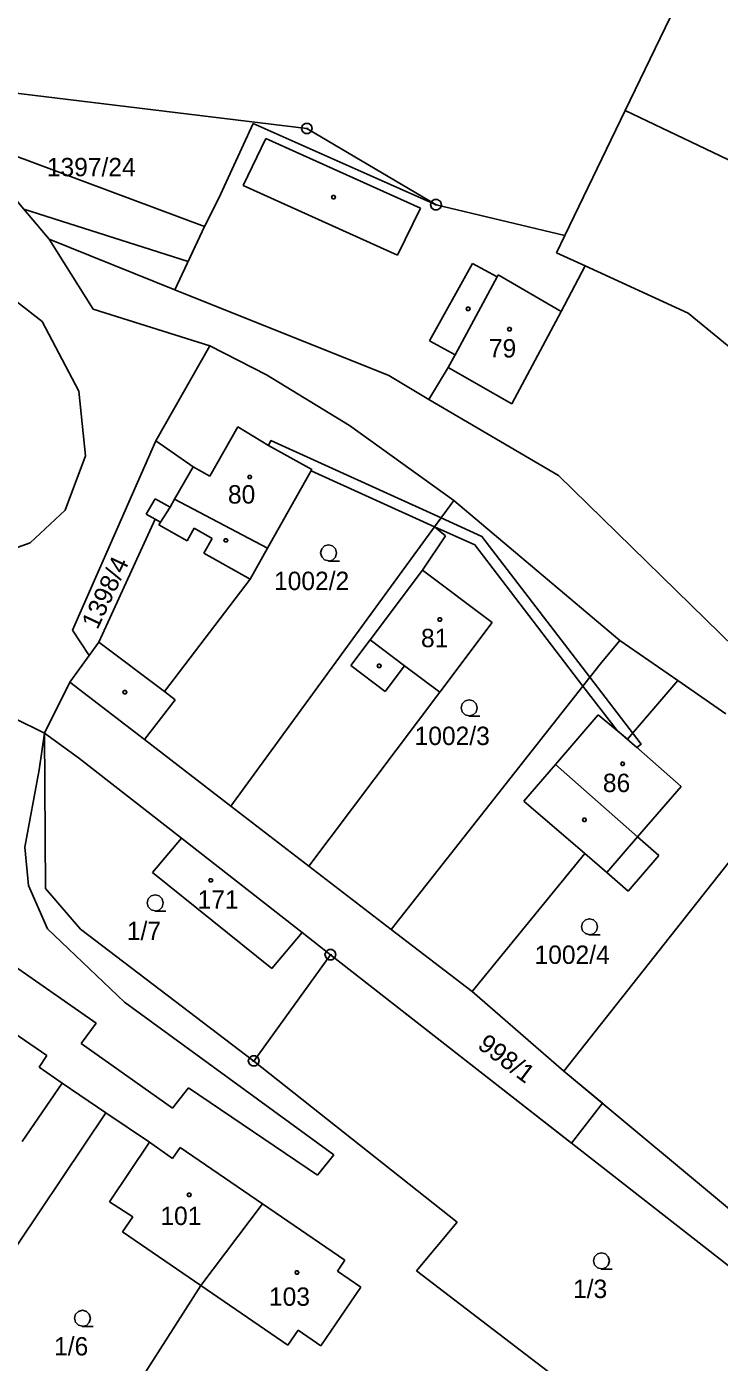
# Model space of a CAD drawing. Extents: x -850689 to -847910, y -1058374 to -1054747.
# Drawn here: x -849251.2 to -849187.1, y -1056373.6 to -1056250.1 of the extents above; entities that cross this region are included whole.
import ezdxf

# ---------------------------------------------------------------- set-up
doc = ezdxf.new("R2010")
doc.units = 0
for name, color, linetype in [('KN_BREMENA', 7, 'Continuous'), ('KN_HRANICE', 7, 'Continuous'), ('KN_KULTURY', 7, 'Continuous'), ('KN_MEZNIKY', 7, 'Continuous'), ('KN_PARCELY', 7, 'Continuous'), ('KN_SLUCKY', 7, 'Continuous'), ('KN_STAVEBNI', 7, 'Continuous')]:
    doc.layers.add(name, color=color, linetype=linetype)

# ---------------------------------------------------------------- blocks, each defined once
blk = doc.blocks.new('304')
blk.add_lwpolyline([(0, 0), (-0.38, 0.1), (-0.65, 0.37), (-0.75, 0.74), (-0.65, 1.11), (-0.38, 1.38), (-0.01, 1.48), (0.36, 1.38), (0.63, 1.11), (0.73, 0.73), (0.63, 0.35), (0.36, 0.08), (-0.02, -0.02), (0.98, -0.02)])
blk = doc.blocks.new('402')
blk.add_lwpolyline([(0.09, 0.15), (0.18, 0), (0.09, -0.15), (-0.09, -0.15), (-0.18, 0), (-0.09, 0.15), (0.09, 0.15)])
blk = doc.blocks.new('105')
blk.add_line((-0.12, 0), (0.12, 0))
blk.add_lwpolyline([(0.15, 0.48), (0.4, 0.3), (0.5, 0.01), (0.4, -0.28), (0.15, -0.46), (-0.16, -0.46), (-0.41, -0.28), (-0.51, 0.01), (-0.41, 0.3), (-0.16, 0.48), (0.15, 0.48)])

msp = doc.modelspace()

# ---------------------------------------------------------------- linework, layer by layer
at = {"layer": 'KN_BREMENA'}
for points in [[(-849236.23, -1056271.84), (-849251.43, -1056266.98), (-849257.13, -1056260.24), (-849234.71, -1056268.6)], [(-849228.79, -1056288.86), (-849228.58, -1056288.4), (-849212.84, -1056295.54), (-849213.44, -1056296.36), (-849224.86, -1056291.18), (-849224.8, -1056291.07)], [(-849199.73, -1056311.09), (-849209.71, -1056298.05), (-849213.44, -1056296.36), (-849212.84, -1056295.54), (-849209.07, -1056297.25), (-849199.09, -1056310.27)], [(-849247.18, -1056310.75), (-849240.27, -1056316.03), (-849232.27, -1056322.21), (-849225.06, -1056327.75), (-849217.45, -1056333.6), (-849209.96, -1056339.35), (-849201.5, -1056346.7), (-849197.93, -1056349.68), (-849200.78, -1056353.37), (-849223.07, -1056335.94), (-849225.69, -1056333.89), (-849236.86, -1056325.16), (-849246.38, -1056317.74), (-849249.52, -1056315.45)], [(-849199.09, -1056310.27), (-849194.34, -1056316.47), (-849194.73, -1056316.77), (-849196.56, -1056315.22), (-849199.73, -1056311.09)]]:
    msp.add_lwpolyline(points, close=True, dxfattribs=at)
at = {"layer": 'KN_HRANICE'}
for p, q in [((-849187.73, -1056241.12), (-849195.81, -1056257.87)), ((-849261.46, -1056255.12), (-849225.25, -1056259.54)), ((-849195.81, -1056257.87), (-849201.39, -1056269.43)), ((-849195.81, -1056257.87), (-849167.34, -1056271.45)), ((-849230.23, -1056259.07), (-849233.42, -1056266.05)), ((-849230.23, -1056259.07), (-849213.31, -1056266.59)), ((-849225.25, -1056259.54), (-849213.31, -1056266.59)), ((-849233.42, -1056266.05), (-849234.71, -1056268.6)), ((-849251.43, -1056266.98), (-849249.09, -1056269.78)), ((-849201.39, -1056269.43), (-849213.31, -1056266.59)), ((-849234.71, -1056268.6), (-849237.45, -1056274.45)), ((-849249.09, -1056269.78), (-849245.03, -1056276.25)), ((-849249.09, -1056269.78), (-849237.45, -1056274.45)), ((-849201.39, -1056269.43), (-849202.16, -1056271.02)), ((-849202.16, -1056271.02), (-849199.51, -1056272.24)), ((-849201.75, -1056276.45), (-849199.51, -1056272.24)), ((-849199.51, -1056272.24), (-849189.99, -1056276.6)), ((-849255.38, -1056273.01), (-849249.72, -1056277.39)), ((-849237.45, -1056274.45), (-849217.67, -1056282.38)), ((-849245.03, -1056276.25), (-849234.23, -1056279.63)), ((-849249.72, -1056277.39), (-849246.35, -1056283.83)), ((-849206.29, -1056284.99), (-849201.75, -1056276.45)), ((-849189.99, -1056276.6), (-849174.78, -1056289.12)), ((-849239.22, -1056288.41), (-849234.23, -1056279.63)), ((-849234.23, -1056279.63), (-849228.99, -1056282.32)), ((-849228.99, -1056282.32), (-849221.32, -1056287)), ((-849217.67, -1056282.38), (-849213.98, -1056284.6)), ((-849213.98, -1056284.6), (-849212.18, -1056281.64)), ((-849212.18, -1056281.64), (-849206.29, -1056284.99)), ((-849246.35, -1056283.83), (-849245.71, -1056289.79)), ((-849213.98, -1056284.6), (-849201.97, -1056291.61)), ((-849231.64, -1056287.13), (-849234.22, -1056291.69)), ((-849231.64, -1056287.13), (-849228.79, -1056288.86)), ((-849221.32, -1056287), (-849211.67, -1056293.94)), ((-849246.94, -1056305.93), (-849239.22, -1056288.41)), ((-849239.22, -1056288.41), (-849235.78, -1056290.81)), ((-849245.71, -1056289.79), (-849247.6, -1056294.83)), ((-849228.79, -1056288.86), (-849224.8, -1056291.07)), ((-849237.48, -1056293.82), (-849235.78, -1056290.81)), ((-849234.22, -1056291.69), (-849235.78, -1056290.81)), ((-849224.8, -1056291.07), (-849228.88, -1056298.35)), ((-849161.41, -1056331.37), (-849201.97, -1056291.61)), ((-849247.6, -1056294.83), (-849250.85, -1056297.85)), ((-849240.1, -1056295.2), (-849239.29, -1056293.78)), ((-849239.29, -1056293.78), (-849237.9, -1056294.56)), ((-849237.9, -1056294.56), (-849237.48, -1056293.82)), ((-849211.67, -1056293.94), (-849213.44, -1056296.36)), ((-849211.67, -1056293.94), (-849196.32, -1056306.88)), ((-849244.48, -1056307.03), (-849239.28, -1056295.66)), ((-849240.1, -1056295.2), (-849239.28, -1056295.66)), ((-849213.44, -1056296.36), (-849232.27, -1056322.21)), ((-849214.56, -1056300.37), (-849212.44, -1056297.19)), ((-849212.44, -1056297.19), (-849213.44, -1056296.36)), ((-849250.85, -1056297.85), (-849254.33, -1056299.1)), ((-849228.88, -1056298.35), (-849230.49, -1056301.22)), ((-849208.12, -1056305.21), (-849214.56, -1056300.37)), ((-849230.49, -1056301.22), (-849238.43, -1056311.61)), ((-849246.94, -1056305.93), (-849245.37, -1056308.26)), ((-849208.12, -1056305.21), (-849212.96, -1056311.65)), ((-849245.37, -1056308.26), (-849244.48, -1056307.03)), ((-849196.32, -1056306.88), (-849198.14, -1056309.07)), ((-849190.95, -1056310.59), (-849196.32, -1056306.88)), ((-849247.18, -1056310.75), (-849245.37, -1056308.26)), ((-849217.45, -1056333.6), (-849198.14, -1056309.07)), ((-849249.52, -1056315.45), (-849247.18, -1056310.75)), ((-849240.27, -1056316.03), (-849247.18, -1056310.75)), ((-849195.6, -1056316.01), (-849190.95, -1056310.59)), ((-849186.5, -1056313.66), (-849190.95, -1056310.59)), ((-849238.43, -1056311.61), (-849237.42, -1056312.38)), ((-849212.96, -1056311.65), (-849225.06, -1056327.75)), ((-849237.42, -1056312.38), (-849240.27, -1056316.03)), ((-849252.37, -1056314.02), (-849249.52, -1056315.45)), ((-849249.52, -1056315.45), (-849250, -1056318.83)), ((-849249.41, -1056329.82), (-849249.52, -1056315.45)), ((-849249.52, -1056315.45), (-849246.38, -1056317.74)), ((-849232.27, -1056322.21), (-849240.27, -1056316.03)), ((-849195.6, -1056316.01), (-849190.65, -1056320.37)), ((-849246.38, -1056317.74), (-849236.86, -1056325.16)), ((-849250, -1056318.83), (-849251.32, -1056325.99)), ((-849194.67, -1056325.05), (-849190.65, -1056320.37)), ((-849201.5, -1056346.7), (-849181.26, -1056321.09)), ((-849225.06, -1056327.75), (-849232.27, -1056322.21)), ((-849239.52, -1056328.34), (-849236.86, -1056325.16)), ((-849236.86, -1056325.16), (-849225.69, -1056333.89)), ((-849194.67, -1056325.05), (-849192.7, -1056326.75)), ((-849251.32, -1056325.99), (-849251.01, -1056329.53)), ((-849209.96, -1056339.35), (-849199.56, -1056326.59)), ((-849197.51, -1056328.35), (-849199.56, -1056326.59)), ((-849192.7, -1056326.75), (-849195.53, -1056330.05)), ((-849217.45, -1056333.6), (-849225.06, -1056327.75)), ((-849228.48, -1056337.23), (-849239.52, -1056328.34)), ((-849195.53, -1056330.05), (-849197.51, -1056328.35)), ((-849251.01, -1056329.53), (-849249.23, -1056333.55)), ((-849246.19, -1056333.59), (-849249.41, -1056329.82)), ((-849244.73, -1056342.28), (-849259.75, -1056331.81)), ((-849249.23, -1056333.55), (-849242.11, -1056340.33)), ((-849230.16, -1056345.77), (-849246.19, -1056333.59)), ((-849225.69, -1056333.89), (-849228.48, -1056337.23)), ((-849223.07, -1056335.94), (-849225.69, -1056333.89)), ((-849209.96, -1056339.35), (-849217.45, -1056333.6)), ((-849223.07, -1056335.94), (-849230.16, -1056345.77)), ((-849223.07, -1056335.94), (-849168.88, -1056378.32)), ((-849201.5, -1056346.7), (-849209.96, -1056339.35)), ((-849256.96, -1056340.03), (-849249.3, -1056345.26)), ((-849242.11, -1056340.33), (-849222.76, -1056354.44)), ((-849246.11, -1056344.16), (-849244.73, -1056342.28)), ((-849237.68, -1056350.14), (-849246.11, -1056344.16)), ((-849250.02, -1056346.33), (-849249.3, -1056345.26)), ((-849247.87, -1056347.82), (-849250.02, -1056346.33)), ((-849230.16, -1056345.77), (-849211.36, -1056360.66)), ((-849201.5, -1056346.7), (-849166.49, -1056375.89)), ((-849251.57, -1056353.21), (-849247.87, -1056347.82)), ((-849243.84, -1056350.56), (-849247.87, -1056347.82)), ((-849236.2, -1056348.24), (-849237.68, -1056350.14)), ((-849224.27, -1056356.34), (-849236.2, -1056348.24)), ((-849264.25, -1056380.97), (-849243.84, -1056350.56)), ((-849243.84, -1056350.56), (-849239.82, -1056353.29)), ((-849239.82, -1056353.29), (-849243.49, -1056358.79)), ((-849237.67, -1056354.78), (-849239.82, -1056353.29)), ((-849236.96, -1056353.76), (-849237.67, -1056354.78)), ((-849229.36, -1056358.98), (-849236.96, -1056353.76)), ((-849222.76, -1056354.44), (-849224.27, -1056356.34)), ((-849243.49, -1056358.79), (-849241.35, -1056360.18)), ((-849235.05, -1056366.54), (-849229.36, -1056358.98)), ((-849221.74, -1056364.19), (-849229.36, -1056358.98)), ((-849241.35, -1056360.18), (-849242.29, -1056361.57)), ((-849242.29, -1056361.57), (-849235.05, -1056366.54)), ((-849211.36, -1056360.66), (-849215.1, -1056365.17)), ((-849221.74, -1056364.19), (-849222.41, -1056365.22)), ((-849222.41, -1056365.22), (-849220.26, -1056366.67)), ((-849215.1, -1056365.17), (-849179.95, -1056392.09)), ((-849235.05, -1056366.54), (-849247.17, -1056385.43)), ((-849235.05, -1056366.54), (-849227, -1056372.04)), ((-849220.26, -1056366.67), (-849223.96, -1056372.1)), ((-849226.06, -1056370.67), (-849227, -1056372.04)), ((-849223.96, -1056372.1), (-849226.06, -1056370.67))]:
    msp.add_line(p, q, dxfattribs=at)
at = {"layer": 'KN_SLUCKY'}
for p, q in [((-849229.04, -1056260.47), (-849231.13, -1056264.79)), ((-849229.04, -1056260.47), (-849214.76, -1056266.9)), ((-849216.86, -1056271.25), (-849231.13, -1056264.79)), ((-849214.76, -1056266.9), (-849216.86, -1056271.25)), ((-849209.93, -1056272.01), (-849213.92, -1056279.18)), ((-849207.65, -1056273.25), (-849209.93, -1056272.01)), ((-849211.54, -1056280.46), (-849207.65, -1056273.25)), ((-849207.55, -1056273.07), (-849207.65, -1056273.25)), ((-849201.75, -1056276.45), (-849207.55, -1056273.07)), ((-849213.92, -1056279.18), (-849211.54, -1056280.46)), ((-849211.54, -1056280.46), (-849212.18, -1056281.64)), ((-849238.79, -1056295.94), (-849237.9, -1056294.56)), ((-849237.48, -1056293.82), (-849228.88, -1056298.35)), ((-849239.28, -1056295.66), (-849238.79, -1056295.94)), ((-849238.93, -1056296.18), (-849238.79, -1056295.94)), ((-849236.33, -1056297.65), (-849238.93, -1056296.18)), ((-849235.68, -1056296.5), (-849236.33, -1056297.65)), ((-849234.01, -1056297.45), (-849235.68, -1056296.5)), ((-849234.77, -1056298.8), (-849234.01, -1056297.45)), ((-849230.49, -1056301.22), (-849234.77, -1056298.8)), ((-849214.56, -1056300.37), (-849219.4, -1056306.81)), ((-849244.48, -1056307.03), (-849238.43, -1056311.61)), ((-849219.4, -1056306.81), (-849221.2, -1056309.2)), ((-849219.4, -1056306.81), (-849216.21, -1056309.21)), ((-849221.2, -1056309.2), (-849218.01, -1056311.6)), ((-849218.01, -1056311.6), (-849216.21, -1056309.21)), ((-849216.21, -1056309.21), (-849212.96, -1056311.65)), ((-849198.33, -1056313.77), (-849202.26, -1056318.34)), ((-849198.33, -1056313.77), (-849195.6, -1056316.01)), ((-849202.26, -1056318.34), (-849205.19, -1056321.75)), ((-849194.67, -1056325.05), (-849202.26, -1056318.34)), ((-849199.56, -1056326.59), (-849205.19, -1056321.75)), ((-849197.51, -1056328.35), (-849194.67, -1056325.05))]:
    msp.add_line(p, q, dxfattribs=at)
at = {"layer": 'KN_STAVEBNI'}
for p, q in [((-849211.54, -1056280.46), (-849207.65, -1056273.25)), ((-849207.55, -1056273.07), (-849207.65, -1056273.25)), ((-849201.75, -1056276.45), (-849207.55, -1056273.07)), ((-849206.29, -1056284.99), (-849201.75, -1056276.45)), ((-849211.54, -1056280.46), (-849212.18, -1056281.64)), ((-849212.18, -1056281.64), (-849206.29, -1056284.99)), ((-849231.64, -1056287.13), (-849234.22, -1056291.69)), ((-849231.64, -1056287.13), (-849228.79, -1056288.86)), ((-849228.79, -1056288.86), (-849224.8, -1056291.07)), ((-849237.48, -1056293.82), (-849235.78, -1056290.81)), ((-849234.22, -1056291.69), (-849235.78, -1056290.81)), ((-849224.8, -1056291.07), (-849228.88, -1056298.35)), ((-849237.48, -1056293.82), (-849228.88, -1056298.35)), ((-849214.56, -1056300.37), (-849219.4, -1056306.81)), ((-849208.12, -1056305.21), (-849214.56, -1056300.37)), ((-849208.12, -1056305.21), (-849212.96, -1056311.65)), ((-849219.4, -1056306.81), (-849216.21, -1056309.21)), ((-849216.21, -1056309.21), (-849212.96, -1056311.65)), ((-849198.33, -1056313.77), (-849202.26, -1056318.34)), ((-849198.33, -1056313.77), (-849195.6, -1056316.01)), ((-849195.6, -1056316.01), (-849190.65, -1056320.37)), ((-849194.67, -1056325.05), (-849202.26, -1056318.34)), ((-849194.67, -1056325.05), (-849190.65, -1056320.37)), ((-849239.52, -1056328.34), (-849236.86, -1056325.16)), ((-849236.86, -1056325.16), (-849225.69, -1056333.89)), ((-849228.48, -1056337.23), (-849239.52, -1056328.34)), ((-849225.69, -1056333.89), (-849228.48, -1056337.23)), ((-849256.96, -1056340.03), (-849249.3, -1056345.26)), ((-849250.02, -1056346.33), (-849249.3, -1056345.26)), ((-849247.87, -1056347.82), (-849250.02, -1056346.33)), ((-849251.57, -1056353.21), (-849247.87, -1056347.82)), ((-849239.82, -1056353.29), (-849243.49, -1056358.79)), ((-849237.67, -1056354.78), (-849239.82, -1056353.29)), ((-849236.96, -1056353.76), (-849237.67, -1056354.78)), ((-849229.36, -1056358.98), (-849236.96, -1056353.76)), ((-849243.49, -1056358.79), (-849241.35, -1056360.18)), ((-849235.05, -1056366.54), (-849229.36, -1056358.98)), ((-849235.05, -1056366.54), (-849229.36, -1056358.98)), ((-849221.74, -1056364.19), (-849229.36, -1056358.98)), ((-849241.35, -1056360.18), (-849242.29, -1056361.57)), ((-849242.29, -1056361.57), (-849235.05, -1056366.54)), ((-849221.74, -1056364.19), (-849222.41, -1056365.22)), ((-849222.41, -1056365.22), (-849220.26, -1056366.67)), ((-849235.05, -1056366.54), (-849227, -1056372.04)), ((-849220.26, -1056366.67), (-849223.96, -1056372.1)), ((-849226.06, -1056370.67), (-849227, -1056372.04)), ((-849223.96, -1056372.1), (-849226.06, -1056370.67))]:
    msp.add_line(p, q, dxfattribs=at)

# ---------------------------------------------------------------- block references
at = {"layer": 'KN_KULTURY'}
for name, p in [('402', (-849222.78, -1056265.88)), ('402', (-849210.34, -1056276.22)), ('402', (-849206.51, -1056278.1)), ('402', (-849230.54, -1056291.76)), ('402', (-849232.74, -1056297.62)), ('304', (-849223.23, -1056299.52)), ('402', (-849212.96, -1056304.95)), ('402', (-849218.56, -1056309.23)), ('402', (-849242.08, -1056311.66)), ('304', (-849210.23, -1056313.85)), ('402', (-849196.05, -1056318.28)), ('402', (-849199.59, -1056323.47)), ('402', (-849234.14, -1056329.06)), ('304', (-849239.27, -1056331.89)), ('304', (-849199.1, -1056334.09)), ('402', (-849236.13, -1056358.15)), ('304', (-849198.01, -1056364.99)), ('402', (-849226.17, -1056365.32)), ('304', (-849246, -1056370.3))]:
    msp.add_blockref(name, p, dxfattribs=at)
at = {"layer": 'KN_MEZNIKY'}
for p in [(-849225.25, -1056259.54), (-849213.31, -1056266.59), (-849223.07, -1056335.94), (-849230.16, -1056345.77)]:
    msp.add_blockref('105', p, dxfattribs=at)

# ---------------------------------------------------------------- texts
at = {"layer": 'KN_PARCELY'}
for s, p in [('1397/24', (-849249.3, -1056263.95)), ('79', (-849208.42, -1056280.71)), ('80', (-849232.55, -1056294.22)), ('1002/2', (-849228.29, -1056302.22)), ('81', (-849214.7, -1056307.5)), ('1002/3', (-849215.29, -1056316.55)), ('86', (-849197.88, -1056320.9)), ('171', (-849235.36, -1056331.69)), ('1/7', (-849241.9, -1056334.59)), ('1002/4', (-849204.2, -1056336.79)), ('101', (-849238.8, -1056360.94)), ('1/3', (-849200.64, -1056367.69)), ('103', (-849228.76, -1056368.41)), ('1/6', (-849248.63, -1056373))]:
    msp.add_text(s, height=1.7, dxfattribs=at).set_placement(p)
for s, rotation, p in [('1398/4', 64.859, (-849244.62, -1056305.95)), ('998/1', 323.205, (-849209.57, -1056344.51))]:
    msp.add_text(s, height=1.7, rotation=rotation, dxfattribs=at).set_placement(p)

doc.saveas('drawing.dxf')
